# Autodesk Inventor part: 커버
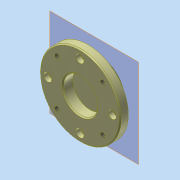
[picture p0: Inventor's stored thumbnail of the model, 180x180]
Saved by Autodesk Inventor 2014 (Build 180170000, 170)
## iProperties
Created: 2023-03
Part Number: 커버
Material: 강철
Document SubType Name: Modeling
Designer: mdu-01
Density: 1 g/cm^3
Appearance: 알루미늄 - 평지(1)
Author: mdu-01
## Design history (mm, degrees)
sketch "스케치1"
  geometry: L1 (0, 0)-(0, 20); L2 (0, 20)-(24, 20); L3 (25, 8)-(40, 8); L4 (40, 8)-(40, 1); L5 (39, 0)-(18, 0); L6 (17, 1)-(17, 10); L7 (17, 10)-(0, 10); L8 (40, 1)-(39, 0); L9 (24, 20)-(25, 19); L10 (25, 16.35)-(22.8, 16.35); L11 (22, 15.55)-(22, 12.45); L12 (22.8, 11.65)-(25, 11.65); L13 (22, 14)-(25, 14); L14 (25, 19)-(25, 16.35); L15 (25, 11.65)-(25, 8); L16 (25, 9)-(25, 62) reference; L17 (40, 8)-(40, 70) reference; L18 (18, 0)-(17, 1); A1 r 0.8 centre (22.8, 12.45) between (22, 12.45) and (22.8, 11.65); A2 r 0.8 centre (22.8, 15.55) between (22.8, 16.35) and (22, 15.55); 3 further points
  constraints: 36 end point, 9 perpendicular, 7 parallel, 7 point on line, 4 point on circle, 4 tangent, 3 collinear, 3 vertical, 2 centre point, 2 midpoint, 1 equal radius, 4 other
  dimensions: "d0" = 20 distance of L1.end L1.start; "d1" = 12 distance between parallel lines of L3 L2; "d2" = 34 diameter of L6 L1; "d3" = 10 distance between parallel lines of L5 L7; "d6" = 1 distance of L4.end point (40, 0); "d7" = 1 distance of L5.start point (40, 0) (= d6); "d8" = 1 distance of L2.end point (25, 20) (= d6); "d9" = 1 distance of L9.end point (25, 20) (= d8); "d11" = 6 distance between parallel lines of L13 L2; "d12" = 4.7 distance between parallel lines of L12 L10; "d13" = 44 diameter of L11 L1; "d15" = 0.8 radius of A2; "d17" = 1 distance of L5.end point (17, 0); "d18" = 1 distance of L6.start point (17, 0) (= d17)
revolve "회전1" sketch "스케치1" stored, may be unused: angle "d16" = 90 deg
sketch "스케치2"
  geometry: C1 r 1.621 at (0, 32) reference; C2 r 1.621 at (0, 32) reference; 1 further point
hole "구멍1" sketch "스케치2" at (0, 32) diameter "d19" = 4.5; stored, may be unused: countersink angle "d23" = 82 deg, drill point angle "d25" = 118 deg; dims "d20" = 6, "d21" = 8, "d22" = 4.6, "d24" = 8
sketch "스케치3"
  geometry: C1 r 4 at (0, 32) reference; A1 r 32 centre (0, 0) between (0, 32) and (-22.627, 22.627); 1 further point
  constraints: 2 point on circle, 1 centre point, 1 coincident
  dimensions: "d26" = 45 deg dimension on A1.centre A1.end C1.centre
hole "구멍2" sketch "스케치3" at (-22.627, 22.627) diameter "d27" = 4.917; stored, may be unused: countersink angle "d31" = 82 deg, drill point angle "d33" = 118 deg; dims "d28" = 8, "d29" = 8, "d30" = 4.6, "d32" = 8
node "작업 평면1"
node "솔리드1"
pattern_circular "원형 패턴1" dims angle "d35" = 360 deg
node "참조1"
node "참조2"
